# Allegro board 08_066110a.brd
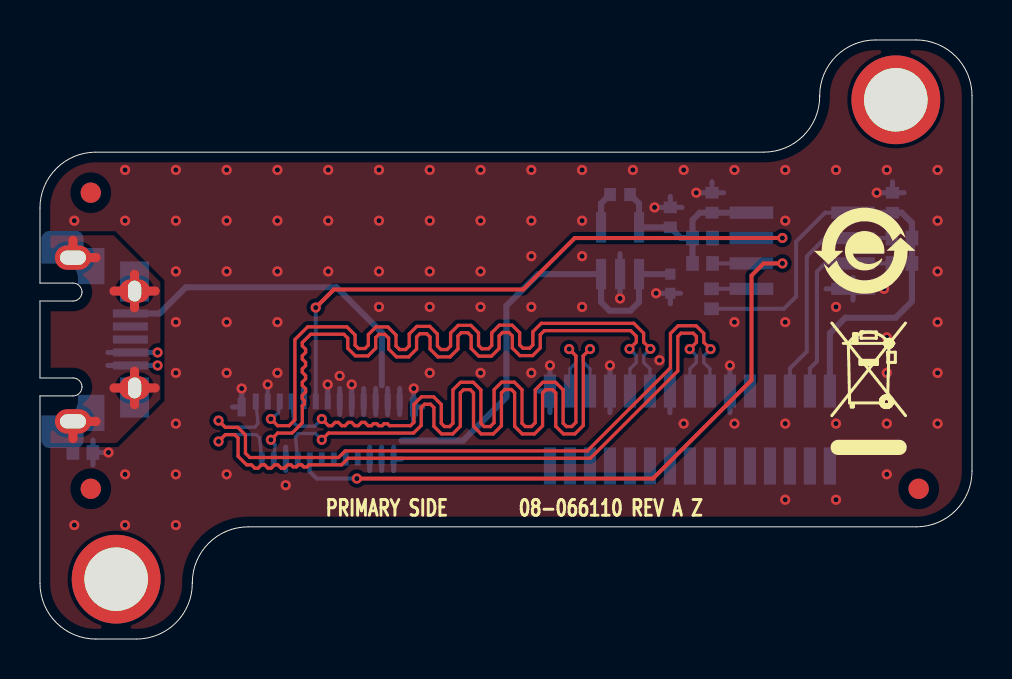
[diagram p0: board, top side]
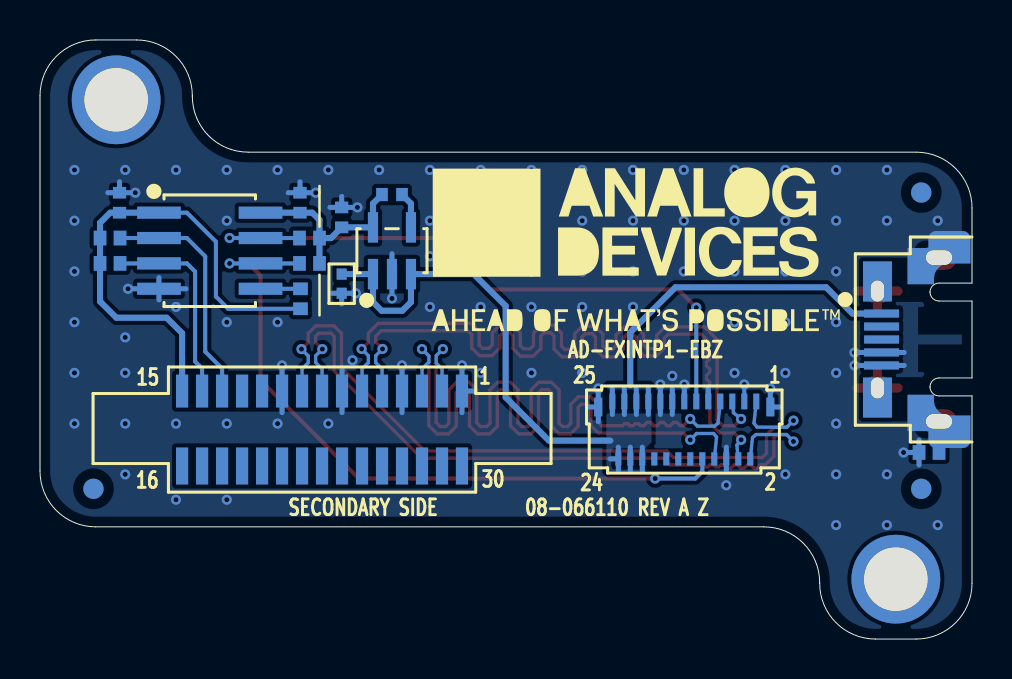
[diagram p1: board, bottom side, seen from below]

Outline 46.62 x 29.99 mm; copper layers: TOP, L2_GND, L3_GND, BOTTOM. Coordinates in mm from the lower left corner of the outline.
Outline path: 0,21.58 0,17.82 1.65,17.82 arc(1.97,17.69) 2.1,17.37 2.1,17.37 arc(1.97,17.05) 1.65,16.92 0,16.92 0,13.07 1.65,13.07 arc(1.97,12.94) 2.1,12.62 2.1,12.62 arc(1.97,12.3) 1.65,12.17 0,12.17 0,2.79 arc(0.82,0.82) 2.79,0 4.83,0 arc(6.8,0.82) 7.62,2.79 7.62,2.82 arc(8.44,4.8) 10.41,5.62 43.83,5.62 arc(45.8,6.44) 46.62,8.41 46.62,27.2 arc(45.8,29.18) 43.83,29.99 41.79,29.99 arc(39.82,29.18) 39,27.2 39,27.17 arc(38.18,25.2) 36.21,24.38 2.79,24.38 arc(0.82,23.56) 0,21.58

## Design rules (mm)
constraint set DEFAULT: min track width 0.203
net group MIPI: nets MIPI_CLKN MIPI_CLKP MIPI_DATA0N MIPI_DATA0P MIPI_DATA1N MIPI_DATA1P

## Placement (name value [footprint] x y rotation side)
C1  0.1uF  [C0402]  42.64 21.85 90 bottom
C2  0.1uF  [C0402]  33.61 21.85 90 bottom
C3  1uF  [C0402H22]  31.53 17.79 270 bottom
C4  0.01uF  [C0402]  29.01 22.25 0 bottom
C5  10uF  [C0402]  31.53 21.11 90 bottom
NOREF  -  []  0 12.17 0 top
NOREF#2  -  []  0 2.79 0 top
NOREF#3  -  []  0 9.66 0 top
NOREF#4  -  []  2.79 0 0 top
NOREF#5  -  []  10.13 157.62 0 top
NOREF#6  -  []  -220.75 -151.86 0 top
NOREF#7  -  []  -6.38 76.59 0 top
NOREF#8  -  []  10.41 5.62 0 top
NOREF#9  -  []  0 17.82 0 top
NOREF#10  -  []  46.62 8.41 0 top
NOREF#11  -  []  2.79 24.38 0 top
NOREF#12  -  []  46.62 5.62 90 top
NOREF#13  -  [unnamed#2]  42.81 27 0 top
NOREF#14  -  []  7.62 2.79 0 top
NOREF#15  -  []  -1.13 14.95 0 top
NOREF#16  -  []  0 24.38 270 top
NOREF#17  -  []  43.83 5.62 0 top
NOREF#18  -  []  4.83 0 0 top
NOREF#19  -  []  0 21.58 0 top
NOREF#20  -  []  3.81 3 0 top
NOREF#21  -  []  41.25 19.44 0 top
NOREF#22  -  []  -24.16 277.25 0 top
NOREF#23  -  []  -89 -87.85 0 top
NOREF#24  -  []  -89 -87.85 0 top
NOREF#25  -  [unnamed#2]  2.54 22.35 0 top
NOREF#26  -  []  0 21.58 0 top
NOREF#27  -  []  41.25 9.28 0 top
NOREF#28  -  [unnamed#2]  2.54 7.52 0 top
NOREF#29  -  []  0.75 23.49 0 top
NOREF#30  -  [unnamed#2]  43.95 7.52 0 top
NOREF#31  -  [unnamed#2]  3.81 3 0 top
NOREF#32  -  []  4.83 0 90 top
NOREF#33  -  []  2.79 0 0 top
NOREF#34  -  []  0 2.79 0 top
NOREF#35  -  []  -89 -87.85 0 top
NOREF#36  -  []  25.07 45.27 0 top
NOREF#37  -  []  36.48 32.34 270 top
NOREF#38  -  []  158.72 100.08 0 top
NOREF#39  -  []  0 0 0 top
NOREF#40  -  []  0 15.2 0 top
NOREF#41  -  []  46.62 29.99 180 top
NOREF#42  -  []  9.72 153.73 0 top
NOREF#43  -  []  -45.54 133.53 0 top
NOREF#44  -  []  22.2 155.08 0 top
NOREF#45  -  []  3.81 3 0 top
NOREF#46  -  [unnamed#2]  2.54 7.52 180 bottom
NOREF#47  -  []  17.38 19.48 180 bottom
NOREF#48  -  [unnamed#2]  2.54 22.36 180 bottom
NOREF#49  -  []  148.2 286.29 180 bottom
NOREF#50  -  [unnamed#2]  43.94 7.52 180 bottom
P1  1-1734248-5  [CNTE1-1734248-5]  32.51 10.54 0 bottom
P2  FH26W-25S-0.3SHW(60)  [CNHRSFH26W-25S-03SHW]  14.39 10.43 0 bottom
P3  10103592-0001LF  [CNFCI10103592-0001LF]  1.82 15 270 bottom
R1  100K  [R0402]  2.15 9.34 0 bottom
R2  10K  [R0402]  43.12 18.81 180 bottom
R3  10K  [R0402]  43.12 20.08 180 bottom
R4  10K  [R0402]  33.59 17.04 90 bottom
R5  10K  [R0402]  33.14 20.08 0 bottom
R6  10K  [R0402]  33.14 18.81 0 bottom
U1  NLSX4373DR2G  [SO8]  38.13 19.44 270 bottom
U2  LT1761ES5-1.8#TRPBF  [TSOT-5]  29.01 19.44 180 bottom

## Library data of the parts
C1 C2 = CAP: User Part Number: UPN; Tolerance: 10; alternate symbols: (); part number: CAP_SM-0.1UF,16V,10,E028141,C0402; tolerance: 10
C3 = CAP: Tolerance: 20; User Part Number: UPN; alternate symbols: (); part number: CAP_SM-1UF,25V,20,E028570,C0402H22; tolerance: 20
C4 = CAP: User Part Number: UPN; Tolerance: 10; alternate symbols: (); part number: CAP_SM-0.01UF,50V,10,E019413,C0402; tolerance: 10
C5 = CAP: User Part Number: UPN; Tolerance: 20; alternate symbols: (); part number: CAP_SM-10UF,4V,20,E025098,C0402; tolerance: 20
P1 = CN30P_V2: User Part Number: UPN; Tolerance: N/A; alternate symbols: (); part number: CN30P_V2_SM-1-1734248-5,E033905,CNTE1-1734248-5; tolerance: N/A
P2 = CN25P_2GND: User Part Number: UPN; Tolerance: N/A; alternate symbols: (); part number: CN25P_2GND_SM-FH26W-25S-0.3SHW(60),E028900,CNHRSFH26W-25S-03SHW; tolerance: N/A
P3 = CN5P_4PSHLD: User Part Number: UPN; Tolerance: N/A; alternate symbols: (); part number: CN5P_4PSHLD_SM-10103592-0001LF,E021325,CNFCI10103592-0001LF; tolerance: N/A
R1 = RES: User Part Number: UPN; Tolerance: 5; alternate symbols: (R0402L); part number: RES_SM-100K,E003464,1/10W,5,R0402; tolerance: 5
R2-R6 = RES: User Part Number: UPN; Tolerance: 1; alternate symbols: (R0402L,R0402L_ALT); part number: RES_SM-10K,E003751,1/10W,1,R0402; tolerance: 1
U1 = ICNLSX4373: Tolerance: N/A; User Part Number: UPN; alternate symbols: (); part number: ICNLSX4373_SM-NLSX4373DR2G,E021744,SO8; tolerance: N/A
U2 = LINLT1761_X: User Part Number: UPN; Tolerance: N/A; alternate symbols: (); part number: LINLT1761_X_SM-LT1761ES5-1.8#TRPBF,E015635,TSOT-5; tolerance: N/A

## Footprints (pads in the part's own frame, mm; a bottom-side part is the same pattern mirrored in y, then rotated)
C0402
  rect 0.584x0.66 smd: 1(-0.5,0) 2(0.5,0)
C0402H22
  rect 0.559x0.508 smd: 1(-0.479,0) 2(0.479,0)
CNFCI10103592-0001LF
  rect 0.406x1.753 smd: 1(-1.3,-2.709) 2(-0.65,-2.709) 3(0,-2.709) 4(0.65,-2.709) 5(1.3,-2.709)
  oval 1.219x1.803 hole 0.711x1.295: 6(-4.1,0.165) 7(4.1,0.165)
  oval 1.168x1.549 hole 1.041x0.66: 8(-2.425,-2.915) 9(2.425,-2.915)
CNHRSFH26W-25S-03SHW
  rect 0.305x0.787 smd: 1(-3.6,-1.469) 3(-3,-1.469) 5(-2.4,-1.469) 7(-1.8,-1.469) 9(-1.2,-1.469) 11(-0.6,-1.469) 13(0,-1.469) 15(0.6,-1.469) 17(1.2,-1.469) 19(1.8,-1.469) 21(2.4,-1.469) 23(3,-1.469) 25(3.6,-1.469)
  rect 0.305x0.66 smd: 2(-3.3,1.405) 4(-2.7,1.405) 6(-2.1,1.405) 8(-1.5,1.405) 10(-0.9,1.405) 12(-0.3,1.405) 14(0.3,1.405) 16(0.9,1.405) 18(1.5,1.405) 20(2.1,1.405) 22(2.7,1.405) 24(3.3,1.405)
  rect 0.406x0.94 smd: GND1(-4.303,-1.193) GND2(4.303,-1.193)
CNTE1-1734248-5
  rect 0.61x1.651 smd: 1(-7,-1.876) 2(-6,-1.876) 3(-5,-1.876) 4(-4,-1.876) 5(-3,-1.876) 6(-2,-1.876) 7(-1,-1.876) 8(0,-1.876) 9(1,-1.876) 10(2,-1.876) 11(3,-1.876) 12(4,-1.876) 13(5,-1.876) 14(6,-1.876) 15(7,-1.876)
  rect 0.61x1.854 smd: 16(7,1.876) 17(6,1.876) 18(5,1.876) 19(4,1.876) 20(3,1.876) 21(2,1.876) 22(1,1.876) 23(0,1.876) 24(-1,1.876) 25(-2,1.876) 26(-3,1.876) 27(-4,1.876) 28(-5,1.876) 29(-6,1.876) 30(-7,1.876)
R0402
  rect 0.635x0.737 smd: 1(-0.5,0) 2(0.5,0)
SO8
  rect 0.61x2.184 smd: 1(-1.905,-2.54) 2(-0.635,-2.54) 3(0.635,-2.54) 4(1.905,-2.54) 5(1.905,2.54) 6(0.635,2.54) 7(-0.635,2.54) 8(-1.905,2.54)
TSOT-5
  rect 0.508x1.524 smd: 1(-0.95,-1.17) 2(0,-1.17) 3(0.95,-1.17) 4(0.95,1.17) 5(-0.95,1.17)
unnamed#2
  round 4.445 hole 3.175 unplated: (0,0)

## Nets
1V8: C2.1 C4.2(N2) C5.1 R5.1 R6.1 U1.8 U2.5
3V3_RPI: C1.1 P1.15 R2.1 R3.1 R4.1 U1.1(VL)
DGND: C1.2(N2) C2.2(N2) C3.2(N2) C5.2(N2) P1.1 P1.4 P1.7 P1.10 P2.3 P2.6 P2.9(N9) P2.13 P2.15 P2.17 P2.GND1 P2.GND2 P3.4 P3.5(N5) R1.2(N2) U1.4 U2.2
I2C_RPI_SCL: P1.13 R3.2(N2) U1.2
I2C_RPI_SDA: P1.14 R2.2(N2) U1.3
I2C_SCL: P2.11 R5.2(N2) U1.7
I2C_SDA: P2.10 R6.2(N2) U1.6
MIPI_CLKN: P1.8 P2.2
MIPI_CLKP: P1.9(N9) P2.1
MIPI_DATA0N: P1.2 P2.7
MIPI_DATA0P: P1.3 P2.8
MIPI_DATA1N: P1.5 P2.4
MIPI_DATA1P: P1.6 P2.5
UNNAMED_2_CAP_I51_N1: C4.1 U2.4
UNNAMED_2_CN5P4PSHLD_I48_GND1: P3.6 P3.7 P3.8 P3.9 R1.1
UNNAMED_2_ICNLSX4373_I43_EN: R4.2(N2) U1.5
USB_5V: C3.1 P2.19 P2.20 P2.21 P2.22 P2.23 P2.24 P2.25 P3.1 U2.1 U2.3(SHDN_N)

Pads without a net: P1 11 12 16 17 18 19 20 21 22 23 24 25 26 27 28 29 30; P2 12 14 16 18; P3 2 3

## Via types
v1: diameter 0.508, hole 0.254, TOP to BOTTOM, 113 vias

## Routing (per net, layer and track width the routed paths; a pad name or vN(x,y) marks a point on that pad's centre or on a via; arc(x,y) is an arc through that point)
1V8: length 10
  BOTTOM w0.305: U1.8 C2.1 33,21.35 32.64,20.98 R5.1 ; R6.1 R5.1 ; R5.1 32.06,20.08 C5.1 U2.5 29.96,21.8 C4.2
3V3_RPI: length 25.4
  BOTTOM w0.203: R4.1 37.21,16.54 37.82,17.15 37.82,19.9 39.27,21.35 U1.1
  BOTTOM w0.305: U1.1 C1.1 43.11,21.35 43.62,20.84 R3.1 R2.1 43.62,16.9 42.8,16.09 40.28,16.09 39.51,15.31 P1.15
DGND: length 37.1
  BOTTOM w0.203: P2.3 v1(11.39,12.74)
  BOTTOM w0.254: 24.95,12.42 P1.1 ; P1.1 25.51,11.34 ; P1.1 25.51,13.5 ; 10.09,12.34 P2.GND1 9.63,11.62 ; 5.65,14.35 P3.4 3.39,14.35 ; P2.9 13.19,12.54 ; 28.51,13.5 P1.4 28.51,11.34 ; C2.2 34.2,22.35 ; C2.2 33.03,22.35 ; C2.2 33.61,22.89 ; R1.2 3.22,9.34 ; R1.2 2.65,8.72 ; R1.2 2.65,9.96 ; 14.99,11.25 P2.15 14.99,12.54 ; 12.29,8.44 P2.6 12.29,9.6 ; C1.2 43.23,22.35 ; C1.2 42.64,22.89 ; C1.2 42.06,22.35 ; 31.51,13.5 P1.7 31.51,11.34 ; U1.4 40.67,18.1 ; U1.4 40.67,16.98 ; U1.4 39.32,17.54 ; U1.4 42.01,17.54 ; 29.01,17.25 U2.2 29.01,19.29 ; P2.13 14.39,12.54 ; 15.59,11.25 P2.17 15.59,12.54 ; 31.53,16.78 C3.2 ; C3.2 32.04,17.31 ; C3.2 31.02,17.31 ; 18.69,10.89 P2.GND2 ; P2.GND2 18.69,12.34 ; P2.GND2 19.15,11.62 ; 30.94,21.61 C5.2 ; C5.2 32.11,21.61 ; C5.2 31.53,22.16 ; 5.65,13.7 P3.5 3.39,13.7 ; 34.51,13.5 P1.10 34.51,11.34
  vias: v1(1.72,20.95) v1(1.72,5.71) v1(3.42,9.34) v1(4.26,23.49) v1(4.26,20.95) v1(4.26,8.25) v1(4.26,5.71) v1(5.88,14.35) v1(5.88,13.7) v1(6.8,23.49) v1(6.8,20.95) v1(6.8,18.41) v1(6.8,15.87) v1(6.8,13.33) v1(6.8,10.79) v1(6.8,8.25) v1(6.8,5.71) v1(9.34,23.49) v1(9.34,20.95) v1(9.34,18.41) v1(9.34,15.87) v1(9.34,13.33) v1(9.34,8.25) v1(10.09,12.54) v1(11.88,23.49) v1(11.88,20.95) v1(11.88,18.41) v1(11.88,15.87) v1(11.88,13.33) v1(12.29,7.7) v1(14.42,23.49) v1(14.42,20.95) v1(14.42,18.41) v1(14.39,12.74) v1(14.99,13.17) v1(15.59,12.74) v1(16.96,23.49) v1(16.96,20.95) v1(16.96,18.41) v1(16.96,16.63) v1(18.69,12.54) v1(19.5,23.49) v1(19.5,20.95) v1(19.5,18.41) v1(19.5,16.63) v1(19.5,13.33) v1(22.04,23.49) v1(22.04,20.95) v1(22.04,18.41) v1(22.04,16.63) v1(22.04,13.33) v1(24.58,23.49) v1(24.58,20.95) v1(24.58,19.17) v1(24.58,16.63) v1(24.58,13.33) v1(25.51,13.7) v1(27.12,23.49) v1(27.12,20.95) v1(27.12,19.17) v1(27.12,16.63) v1(28.51,13.7) v1(29.01,17.05) v1(29.66,23.49) v1(30.74,21.61) v1(30.82,17.31) v1(30.99,13.96) v1(32.2,23.49) v1(32.2,10.79) v1(32.83,22.35) v1(34.51,13.7) v1(34.74,23.49) v1(34.74,15.87) v1(34.74,10.79) v1(37.28,23.49) v1(37.28,20.95) v1(37.28,15.87) v1(37.28,10.79) v1(37.28,6.98) v1(39.82,23.49) v1(39.82,16.63) v1(39.82,10.79) v1(39.82,6.98) v1(41.85,22.35) v1(42.22,17.54) v1(42.36,23.49) v1(42.36,15.1) v1(42.36,13.33) v1(42.36,10.79) v1(42.36,8.25) v1(44.9,23.49) v1(44.9,20.95) v1(44.9,18.41) v1(44.9,15.87) v1(44.9,13.33) v1(44.9,10.79)
I2C_RPI_SCL: length 11.7
  BOTTOM w0.203: P1.13 37.51,13.55 38.35,14.39 38.35,19.16 39.27,20.08 U1.2 R3.2
I2C_RPI_SDA: length 10.1
  BOTTOM w0.203: R2.2 U1.3 39.27,18.81 38.86,18.4 38.86,13.9 38.51,13.55 P1.14
I2C_SCL: length 33
  TOP w0.203: v1(13.79,16.59) 14.7,17.5 24.17,17.5 26.75,20.08 36.58,20.08 36.58,20.08 v1(37.14,20.08)
  BOTTOM w0.203: v1(37.14,20.08) 35.59,20.08 U1.7 R5.2 ; v1(13.79,16.59) P2.11
I2C_SDA: length 35.5
  TOP w0.203: v1(37.14,18.81) 36.2,18.81 35.59,18.2 35.59,12.96 30.66,8.03 v1(15.85,8.03)
  BOTTOM w0.203: R6.2 U1.6 v1(37.14,18.81) ; P2.10 13.49,8.39 13.84,8.03 v1(15.85,8.03)
MIPI_CLKN: length 36.1
  TOP w0.165: v1(32.5,14.52) 32.83,14.85 32.83,15.15 32.67,15.31 32.07,15.31 31.9,15.15 31.9,13.42 27.53,9.05 15.42,9.05 15.09,8.72 13.46,8.72 13.36,8.62 13.2,8.62 13.09,8.72 12.93,8.72 12.83,8.62 12.66,8.62 12.56,8.72 12.4,8.72 12.23,8.56 12.07,8.56 11.9,8.72 11.73,8.72 11.57,8.56 11.4,8.56 11.24,8.72 11.07,8.72 10.91,8.56 10.74,8.56 10.58,8.72 10.34,8.72 9.91,9.15 9.91,10.07 9.74,10.23 9.27,10.23 v1(8.93,9.89)
  BOTTOM w0.165: P1.8 32.51,13.53 32.83,13.85 32.83,14.18 v1(32.5,14.52) ; v1(8.93,9.89) 9.28,10.24 10.81,10.24 10.98,10.08 P2.2
MIPI_CLKP: length 36.1
  TOP w0.165: v1(8.93,10.94) 9.27,10.6 9.9,10.6 10.28,10.22 10.28,9.3 10.49,9.09 14.94,9.09 15.27,9.42 27.38,9.42 31.54,13.58 31.54,15.3 31.92,15.68 32.82,15.68 33.2,15.3 33.2,14.85 v1(33.54,14.52)
  BOTTOM w0.165: v1(33.54,14.52) 33.2,14.17 33.2,13.84 33.51,13.53 P1.9 ; P2.1 10.9,10.8 10.75,10.61 9.26,10.61 v1(8.93,10.94)
MIPI_DATA0N: length 36
  TOP w0.165: v1(14.09,11.02) 14.43,10.68 14.6,10.68 14.76,10.85 14.93,10.85 15.09,10.68 15.26,10.68 15.42,10.85 15.59,10.85 15.75,10.68 15.92,10.68 16.08,10.85 16.25,10.85 16.41,10.68 16.58,10.68 16.68,10.78 16.85,10.78 16.95,10.68 17.11,10.68 17.21,10.78 17.38,10.78 17.48,10.68 18.53,10.68 18.7,10.85 18.7,11.75 19.08,12.13 19.69,12.13 20.07,11.75 20.07,10.8 20.24,10.64 20.49,10.64 20.66,10.8 20.66,12.48 21.04,12.86 21.67,12.86 22.05,12.48 22.05,10.8 22.22,10.64 22.52,10.64 22.71,10.83 22.71,12.48 23.09,12.86 23.73,12.86 24.11,12.48 24.11,10.8 24.28,10.64 24.58,10.64 24.77,10.83 24.77,12.48 25.15,12.86 25.79,12.86 26.17,12.48 26.17,10.8 26.33,10.64 26.6,10.64 26.81,10.85 26.81,14.18 v1(26.47,14.52)
  BOTTOM w0.165: v1(26.47,14.52) 26.8,14.19 26.8,13.82 26.51,13.53 P1.2 ; P2.7 12.7,10.8 12.88,10.66 13.73,10.66 v1(14.09,11.02)
MIPI_DATA0P: length 36
  TOP w0.165: v1(14.09,9.98) 14.43,10.31 18.69,10.31 19.07,10.69 19.07,11.59 19.23,11.76 19.54,11.76 19.7,11.59 19.7,10.65 20.08,10.27 20.64,10.27 21.02,10.65 21.02,12.32 21.19,12.49 21.52,12.49 21.68,12.32 21.68,10.65 22.07,10.27 22.68,10.27 23.08,10.68 23.08,12.33 23.25,12.49 23.58,12.49 23.74,12.33 23.74,10.65 24.12,10.27 24.73,10.27 25.14,10.68 25.14,12.32 25.3,12.49 25.63,12.49 25.8,12.32 25.8,10.65 26.18,10.27 26.75,10.27 27.17,10.69 27.17,14.18 v1(27.51,14.52)
  BOTTOM w0.165: v1(27.51,14.52) 27.17,14.17 27.17,13.87 27.51,13.53 P1.3 ; P2.8 12.78,10.11 12.92,10.29 13.78,10.29 v1(14.09,9.98)
MIPI_DATA1N: length 36.1
  TOP w0.165: v1(29.49,14.53) 29.83,14.86 29.83,15.16 29.55,15.44 25.23,15.44 25.02,15.23 25.02,14.57 24.64,14.19 24.01,14.19 23.62,14.57 23.62,15.18 23.46,15.35 23.13,15.35 22.96,15.18 22.96,14.55 22.58,14.16 21.95,14.16 21.57,14.55 21.57,15.17 21.4,15.34 21.07,15.34 20.91,15.17 20.91,14.52 20.51,14.13 19.9,14.13 19.51,14.52 19.51,15.12 19.34,15.29 19,15.29 18.84,15.12 18.84,14.52 18.44,14.13 17.83,14.13 17.44,14.52 17.44,15.07 17.25,15.26 16.96,15.26 16.79,15.09 16.79,14.56 16.41,14.18 15.78,14.18 15.39,14.56 15.39,15.07 15.2,15.26 13.54,15.26 13.12,14.84 13.12,14.68 13.28,14.51 13.28,14.35 13.12,14.18 13.12,14.02 13.28,13.85 13.28,13.69 13.12,13.52 13.12,13.36 13.28,13.19 13.28,13.03 13.12,12.86 13.12,12.7 13.28,12.53 13.28,12.37 13.12,12.2 13.12,12.04 13.22,11.93 13.22,11.77 13.12,11.67 13.12,10.82 12.61,10.31 11.89,10.31 v1(11.55,9.98)
  BOTTOM w0.165: v1(11.55,9.98) 11.76,9.71 P2.4 ; v1(29.49,14.53) 29.83,14.19 29.83,13.84 29.51,13.53 P1.5
MIPI_DATA1P: length 36.1
  TOP w0.165: v1(30.53,14.53) 30.19,14.86 30.19,15.31 29.7,15.81 25.07,15.81 24.65,15.39 24.65,14.72 24.49,14.56 24.16,14.56 23.99,14.72 23.99,15.33 23.61,15.71 22.98,15.71 22.6,15.33 22.6,14.7 22.43,14.53 22.1,14.53 21.94,14.7 21.94,15.32 21.55,15.71 20.92,15.71 20.54,15.32 20.54,14.67 20.36,14.49 20.06,14.49 19.88,14.67 19.88,15.27 19.5,15.65 18.85,15.65 18.47,15.27 18.47,14.67 18.29,14.49 17.99,14.49 17.81,14.67 17.81,15.22 17.4,15.62 16.8,15.62 16.42,15.24 16.42,14.71 16.26,14.55 15.93,14.55 15.76,14.71 15.76,15.22 15.35,15.63 13.39,15.63 12.75,15 12.75,10.98 12.46,10.68 11.89,10.68 v1(11.55,11.02)
  BOTTOM w0.165: P2.5 11.93,11.33 v1(11.55,11.02) ; v1(30.53,14.53) 30.19,14.19 30.19,13.84 30.51,13.53 P1.6
UNNAMED_2_CAP_I51_N1: length 1.8
  BOTTOM w0.305: C4.1 28.06,21.8 U2.4
UNNAMED_2_CN5P4PSHLD_I48_GND1: length 13.1
  TOP w0.457: P3.8 5.76,17.42 ; P3.8 3.7,17.42 ; P3.8 4.73,18.26 ; P3.8 4.73,16.58 ; 1.65,10.03 P3.7 2.81,10.9 ; 3.7,12.57 P3.9 ; P3.9 4.73,13.41 ; P3.9 5.76,12.57 ; P3.9 4.73,11.73 ; 1.65,19.96 P3.6 2.81,19.1
  BOTTOM w0.305: R1.1 P3.7
UNNAMED_2_ICNLSX4373_I43_EN: length 2
  BOTTOM w0.203: R4.2 U1.5
USB_5V: length 48.5
  BOTTOM w0.254: 16.79,11.25 P2.21 16.79,12.54 ; 17.39,11.25 P2.23 17.39,12.54 ; 17.69,8.44 P2.24 ; P2.24 17.69,9.6 ; P2.24 18.1,9.02 ; 17.99,12.54 P2.25 17.99,11.25 ; 16.49,9.6 P2.20 16.49,8.44 ; 17.09,8.44 P2.22 17.09,9.6 ; 16.19,12.54 P2.19 16.19,11.25
  BOTTOM w0.305: 17.1,12.7 17.1,15.35 14.83,17.61 7.29,17.61 5.98,16.3 P3.1 ; 18.09,9.94 21.16,9.94 23.33,12.1 23.33,16.68 24.92,18.27 U2.3 28.06,16.87 28.5,16.44 29.53,16.44 29.96,16.87 U2.1 C3.1

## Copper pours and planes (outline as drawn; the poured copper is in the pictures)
DGND on BOTTOM: 39.51,27.2 40.18,28.82 41.79,29.49 43.83,29.49 45.44,28.82 46.11,27.2 46.11,8.41 45.44,6.8 43.83,6.13 10.41,6.13 8.08,5.16 7.11,2.82 7.11,2.79 6.44,1.18 4.83,0.51 2.79,0.51 1.18,1.18 0.51,2.79 0.51,11.66 1.65,11.66 2.33,11.94 2.33,13.3 1.65,13.58 0.51,13.58 0.51,16.41 1.65,16.41 2.33,16.69 2.33,18.05 1.65,18.33 0.51,18.33 0.51,21.58 1.18,23.2 2.79,23.87 36.21,23.87 38.54,24.84 39.51,27.17 ; 3 cut-outs
UNNAMED_2_CN5P4PSHLD_I48_GND1 on TOP: 0.53,20.21 3.68,20.21 6.02,17.88 6.02,12.01 3.83,9.82 0.53,9.82 0.53,11.66 1.65,11.66 2.33,11.94 2.33,13.3 1.65,13.58 0.53,13.58 0.53,16.41 1.65,16.41 2.33,16.69 2.33,18.05 1.65,18.33 0.53,18.33
USB_5V on BOTTOM: 18.19,12.73 16.13,12.73 16.03,12.63 16.03,9.86 16.33,9.55 16.33,8.41 16.46,8.28 18.16,8.28 18.29,8.41 18.29,12.63

Small or netless copper shapes (teardrops, artwork), in the pictures only: 1 on TOP

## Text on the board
Ref Des/Assembly Bottom: MATE ENTRY
Ref Des/Silkscreen Bottom: AD-FXINTP1-EBZ
User.Comments: WITH LEAD-FREE AND RoHS PCB ASSEMBLY STANDARDS (EU RoHS | DIRECTIVE 2002/95/EC). | 4.   RoHS COMPLIANCE: ASSEMBLY VENDOR SHOULD ASSURE COMPLIANCE | NO COMPONENT INSTALLED ON THE PRIMARY SIDE
DIMENSION: SEE DETAIL A | (TYP, 7 PLCS) | DETAIL A | (REF) | DIA MAX
PAGE_OUTLINE: CUSTOMER EVALUATION Z
User.15: NOTE: ALL IMPEDANCE TOLERANCE +/-10% | LAYER | L1 | L4 | 100 OHMS DP | IMPEDANCE | DP = DIFFERENTIAL PAIR | REFERENCE | L2 | L3 | LINE WIDTH | 6.5MILS | SPACE | 8MILS | IMPEDANCE TABLE
User.17: L2 GND | 08-      -07
User.18: L3 GND | 08-      -08
User.45: FIGURE | SIZE | 10.0 | 125.0 | 41.0x26.0 | 51.0x28.0 | PLATED | NON-PLATED | DRILL CHART: TOP to BOTTOM | ALL UNITS ARE IN MILS | QTY | 113 | 2 | TOLERANCE/NOTES
